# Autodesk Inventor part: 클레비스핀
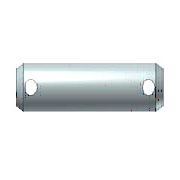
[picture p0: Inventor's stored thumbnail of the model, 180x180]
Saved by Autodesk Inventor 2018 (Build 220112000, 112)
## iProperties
IsCustomPart: 1
Created: 2012-02
Part Number: 클레비스핀
Material: 강철
Description: 머리가 없는 클레비스 핀 B
Document SubType Name: Modeling
Standard: ISO 2340
Designer: mduedu
Standard Revision: Second edition 1986-11-01
Standards Organization: ISO
Language: ko-KR
Size Designation: B - 8 x 45
Categories: <MemberInstance><Categories><Category DisplayName="조임쇠" InternalName="e4da775c-781d-43d5-af7c-5136215cf5a6" Mnemonic="FSTN"><Category DisplayName="핀" InternalNa
Density: 7.85 g/cm^3
Appearance: 반광택
Author: mduedu
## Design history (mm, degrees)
sketch "스케치1"
  geometry: L1 (-4.5, 0)-(-4.5, 4); L2 (-4.5, 4)-(35.5, 4); L3 (35.5, 4)-(35.5, 0); L4 (-4.5, 0)-(35.5, 0); L5 (0, -2)-(0, 5) reference; L6 (-13.5, 0)-(49.5, 0) reference; C1 r 1 at (-1, 0); C2 r 1 at (32, 0)
  constraints: 8 end point, 2 centre point, 2 perpendicular, 2 point on line, 1 collinear, 1 parallel, 1 tangent, 1 vertical
  dimensions: "d0" = 8 diameter of L2 L4 (= NND); "d1" = 40 distance of L1.end L2.end (= NLG); "d2" = 3.5 distance from line of L1 C1.centre (= DIST1); "d3" = 3.5 distance from line of L3 C2.centre (= DIST2); "d4" = 2 diameter of C1 (= BOR1); "d5" = 2 diameter of C2 (= BOR2)
revolve "본체" stored, may be unused: angle "d7" = 90 deg
extrude "구멍1" cut sketch "스케치1" extent not by distance; taper "d6" = 0 deg; stored distance "d8" = 10
extrude "구멍2" cut sketch "스케치1" extent not by distance; taper "d13" = 0 deg; stored distance "d14" = 10
workaxis "Work Axis1"
workaxis "Work Axis2"
workplane "Work Plane1"
node "작업 평면5"
body "Solid1"
chamfer "모따기2" distance "d9" = 2 (= PHH2); stored, may be unused: angle "d10" = 30 deg (= FAWI2), second distance "d40" = 2 (= PHH2)
chamfer "모따기1" distance "d11" = 2 (= PHH1); stored, may be unused: angle "d12" = 30 deg (= FAWI1), second distance "d41" = 2 (= PHH1)
other parameters: "NLG" = 40 [user parameter; used in 1 equation term], "NND" = 8 [user parameter; used in 1 equation term], "PHH1" = 2 [user parameter; used in 3 equation terms], "PHH2" = 2 (= PHH1) [user parameter; used in 2 equation terms], "FAWI1" = 30 deg [user parameter; used in 1 equation term], "FAWI2" = 30 deg [user parameter; used in 1 equation term], "DIST1" = 3.5 [user parameter; used in 4 equation terms], "DIST2" = 3.5 (= DIST1) [user parameter; used in 1 equation term], "BOR1" = 2 [user parameter; used in 4 equation terms], "BOR2" = 2 (= BOR1) [user parameter; used in 1 equation term], "d15" = 0, "d42" = 0, "d43" = 0, "d44" = -4.5 (= -0.5 x BOR1 - DIST1), "d45" = -4.5 (= -0.5 x BOR1 - DIST1), "d47" = 0, "d48" = 0, "d49" = 0, "d50" = 0, "d51" = 0, "d52" = 0
